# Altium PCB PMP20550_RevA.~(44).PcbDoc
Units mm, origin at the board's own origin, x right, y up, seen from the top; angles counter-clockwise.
Board outline 49.95 x 50.01 mm, 2 copper layers (Top Layer, Bottom Layer), stack 1.575 mm thick; 56 components, 23 nets, 129 pads, 17 vias.
Unrouted connection lines stored in the file: 113.
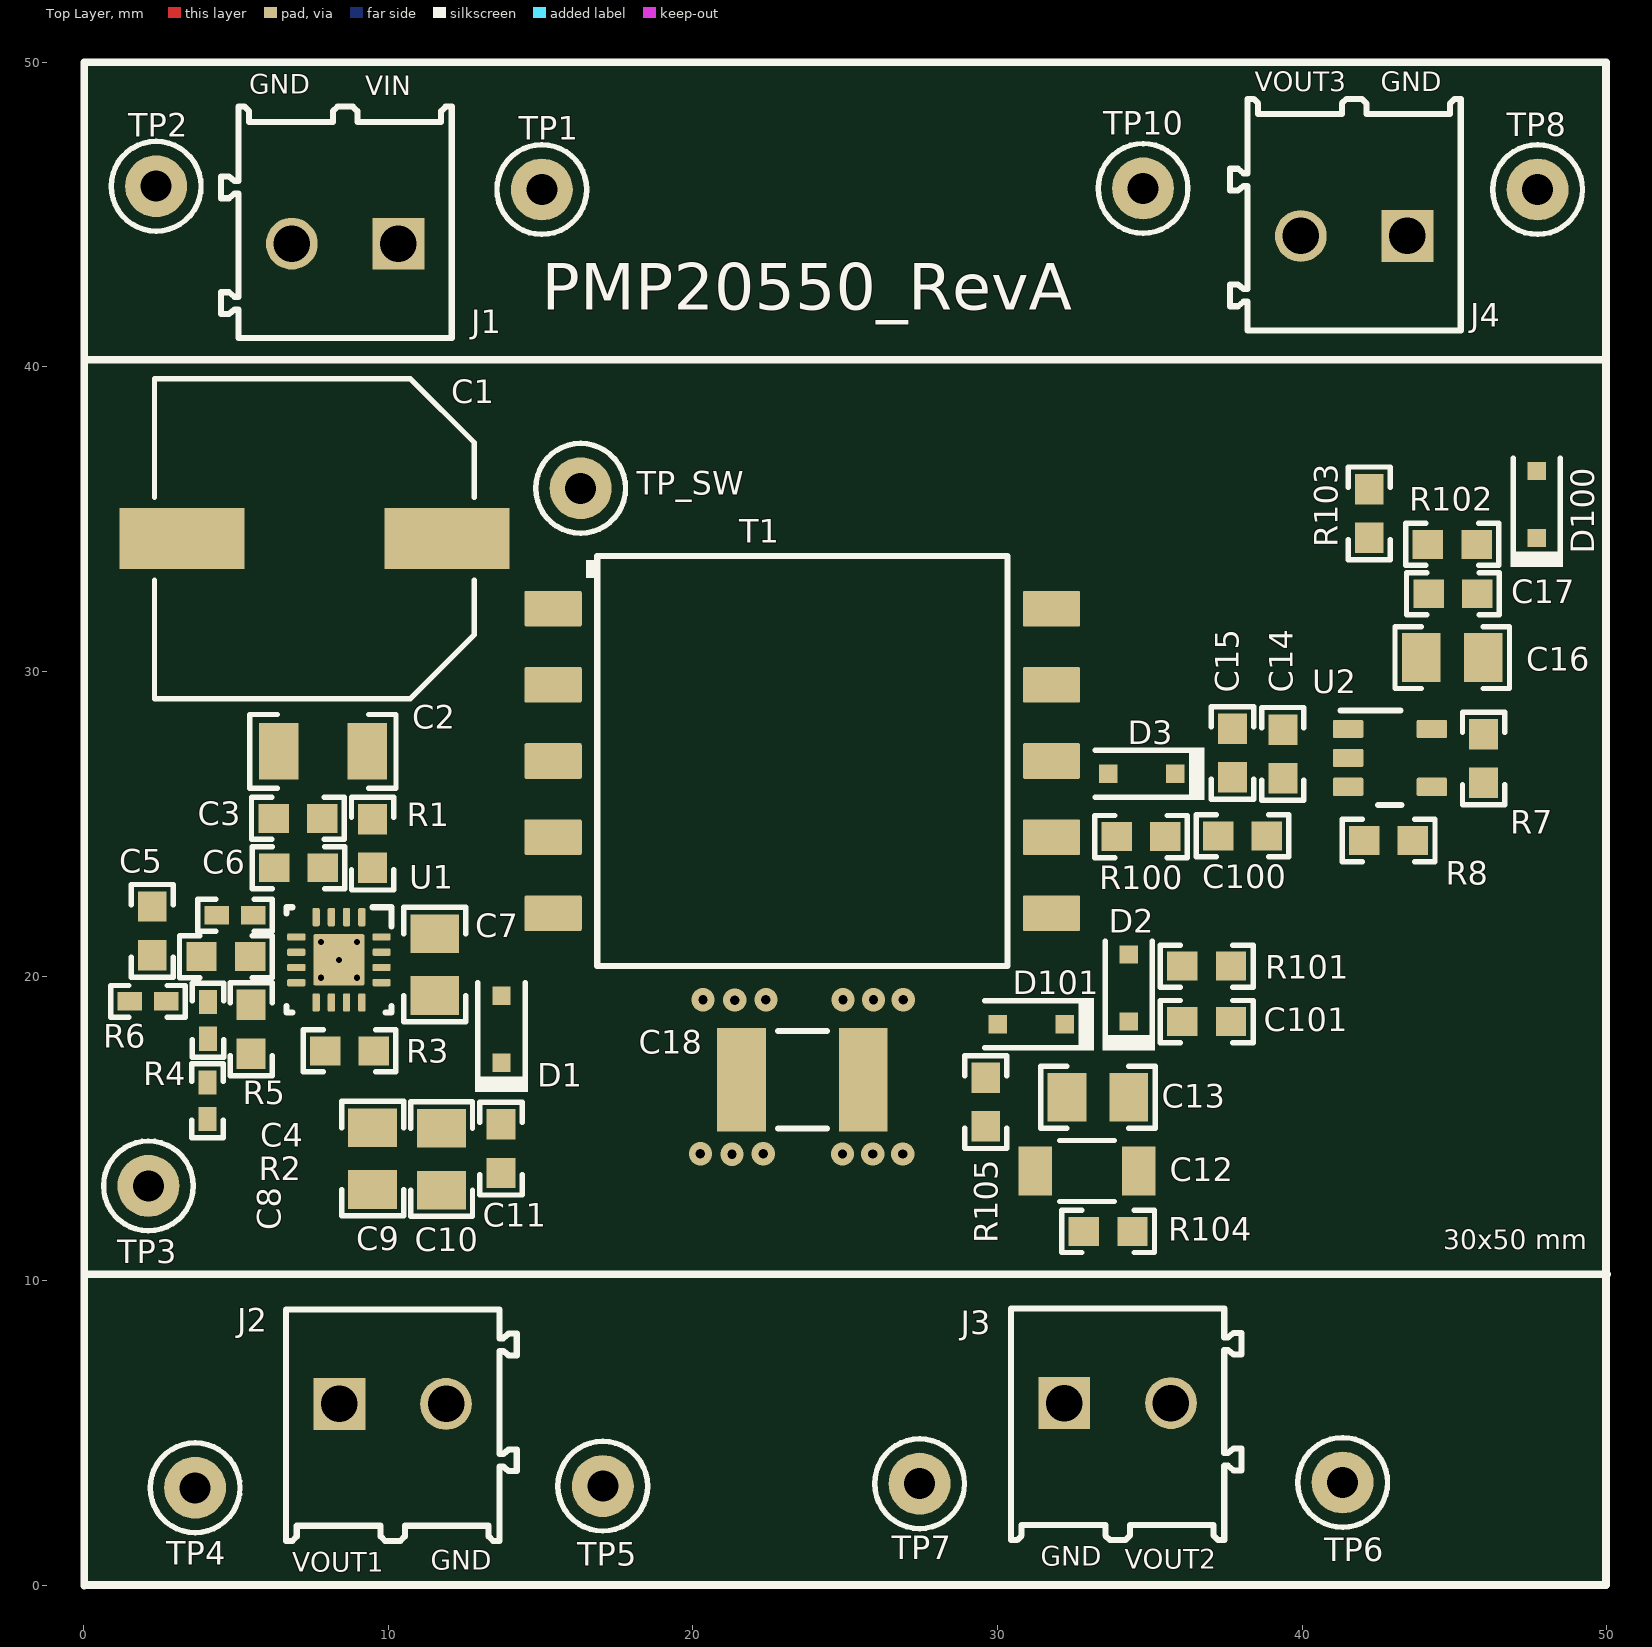
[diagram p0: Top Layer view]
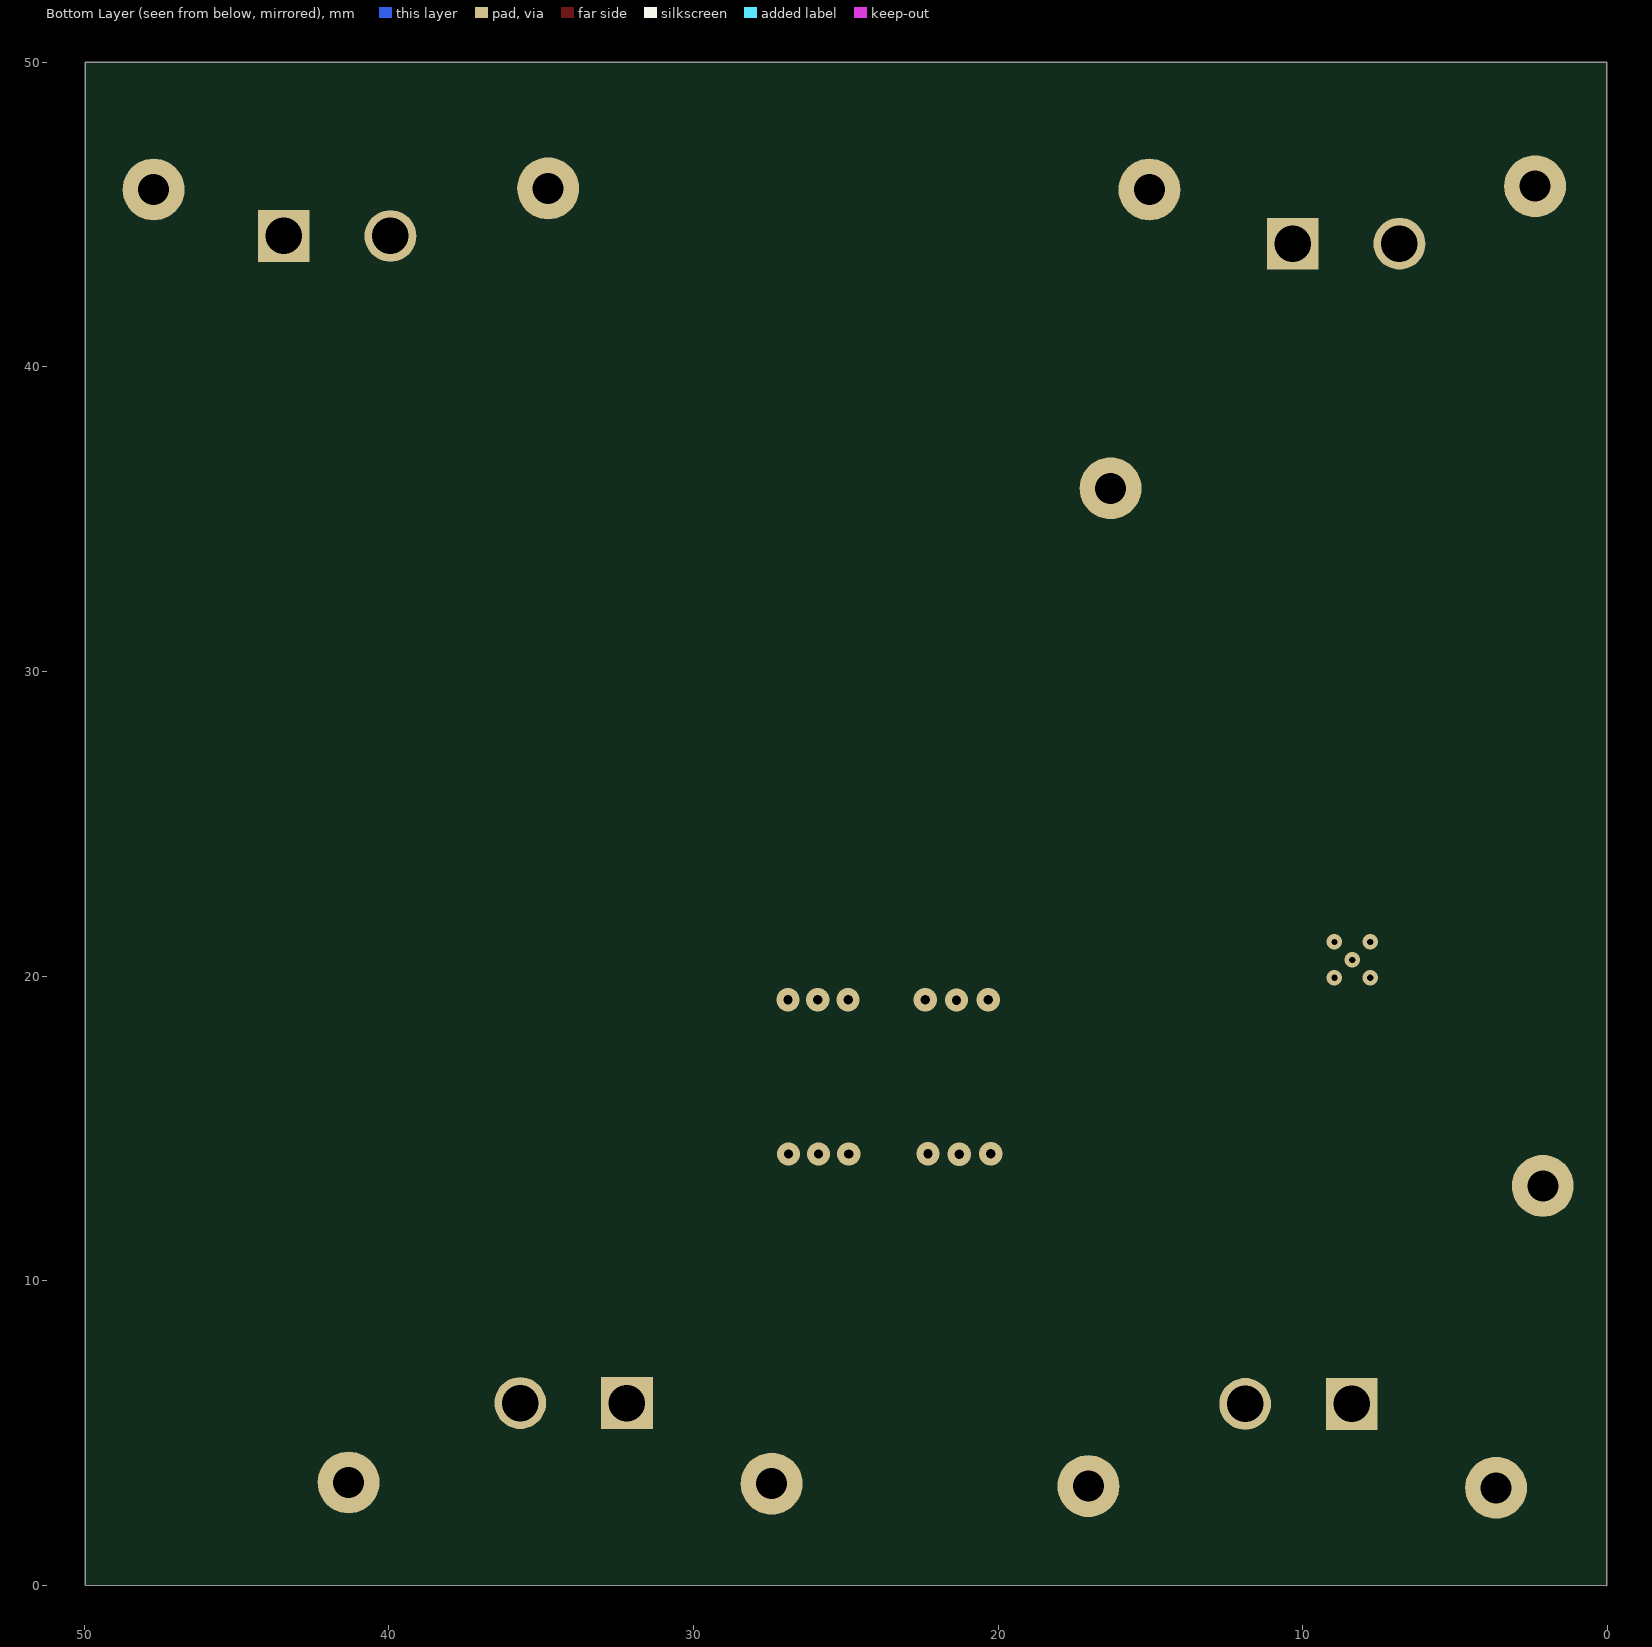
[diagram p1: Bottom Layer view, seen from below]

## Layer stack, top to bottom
Top Solder: solder mask 0.0102, Solder Resist, Dk 3.5
Top Layer: signal copper 0.0356
Dielectric1: core 1.5037, FR-4, Dk 4.8
Bottom Layer: signal copper 0.0356
Bottom Solder: solder mask 0.0102, Solder Resist, Dk 3.5

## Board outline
0.019,-0.011 0.019,49.996 0.021,49.994 49.97,49.994 49.972,49.992 49.972,0.008 49.971,0.01

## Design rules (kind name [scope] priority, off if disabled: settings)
AcuteAngle [All] p1: minimum=4.50000000000000E+0001 checktracksonly=FALSE
AssemblyTestPointUsage [All] p1: valid=2
BoardOutlineClearance BoardOutlineClearance_MountingHoles [OnCopper and InComponentClass('Mounting Holes')] p1: gap=1.016
BoardOutlineClearance BoardOutlineClearance_Poly [OnCopper and IsPoly] p2: gap=0.635
BoardOutlineClearance [OnCopper and Not InComponentClass('Logo') and not InComponentClass('FiducialMark') and not InRegion(1000,500,4000,800) and not InPoly] p3: gap=1.016
Clearance Clearance_Keepouts [((IsTrack Or IsArc) And Not InPoly) And IsFree and IsKeepOut vs ((IsTrack Or IsArc) And Not InPoly) And IsFree and IsKeepOut] p1: gap=0
Clearance Clearance_Poly [InPolygon] p2: gap=0.635
Clearance [All] p3: gap=0.2
ComponentClearance ComponentClearance_MountingHoles_FiducialMarks [InComponentClass('Mounting Holes') vs InComponentClass('FiducialMark')] p1: gap=1.27 collisioncheckmode=3 verticalgap=0.254 showdistances=FALSE
ComponentClearance ComponentClearance_Shunt [InComponentClass('Header') vs InComponentClass('Shunt')] p2: gap=0 collisioncheckmode=3 verticalgap=0 showdistances=FALSE
ComponentClearance ComponentClearance_Logo [InComponentClass('Logo')] p3: gap=1.27 collisioncheckmode=3 verticalgap=0.254 showdistances=FALSE
ComponentClearance ComponentClearance_ScrewToNut [(HasFootprint('NY PMS 440 0025 PH')) vs (HasFootprint('Keystone_1902C'))] p4: gap=0.127 collisioncheckmode=3 verticalgap=0.254 showdistances=FALSE
ComponentClearance ComponentClearance_MountingHoles [InComponentClass('Mounting Holes')] p5: gap=6.35 collisioncheckmode=3 verticalgap=2540 showdistances=FALSE
ComponentClearance ComponentClearance_SmallPassives [HasFootprint('0201*') or HasFootprint('0402*') or HasFootprint('0508') or HasFootprint('0603*') or HasFootprint('0612') or HasFootprint('0805*') or HasFootprint('0815*') or HasFootprint('0830*') or HasFootprint('1206*') or HasFootprint('1210*') or HasFootprint('1808*') or HasFootprint('1812*') or HasFootprint('1825*') or HasFootprint('2010*') or HasFootprint('2220*') or HasFootprint('2225*') or HasFootprint('2512*') or HasFootprint('2728*') or HasFootprint('3518*') vs HasFootprint('0201*') or HasFootprint('0402*') or HasFootprint('0508') or HasFootprint('0603*') or HasFootprint('0612') or HasFootprint('0805*') or HasFootprint('0815*') or HasFootprint('0830*') or HasFootprint('1206*') or HasFootprint('1210*') or HasFootprint('1808*') or HasFootprint('1812*') or HasFootprint('1825*') or HasFootprint('2010*') or HasFootprint('2220*') or HasFootprint('2225*') or HasFootprint('2512*') or HasFootprint('2728*') or HasFootprint('3518*')] p6: gap=0.38 collisioncheckmode=3 verticalgap=0.254 showdistances=FALSE
ComponentClearance ComponentClearance_THtoSMT [IsThruComponent vs IsSMTComponent] p7: gap=1.016 collisioncheckmode=3 verticalgap=0.762 showdistances=FALSE
ComponentClearance ComponentClearance_THtoTH [IsThruComponent vs IsThruComponent] p8: gap=0.762 collisioncheckmode=3 verticalgap=0.762 showdistances=FALSE
ComponentClearance [All] p9: gap=0.762 collisioncheckmode=3 verticalgap=0.254 showdistances=FALSE
DiffPairsRouting [All] p1: maxlimit=2.54 minlimit=0.254 mostfreqgap=0.254 toplayer_minwidth=0.381 toplayer_maxwidth=0.381 toplayer_prefwidth=0.381 bottomlayer_minwidth=0.381 bottomlayer_maxwidth=0.381 bottomlayer_prefwidth=0.381 maxuncoupledlength=25.4
FabricationTestPointUsage TestPointUsage [All] p1: valid=2 allowmultiple=FALSE
FabricationTestpoint Testpoint [All] p1: side=3 testpointundercomponent=TRUE minsize=1.016 maxsize=2.54 preferedsize=1.524 minholesize=0 maxholesize=1.016 preferedholesize=0.813 testpointgrid=0.025 allowsidetop=TRUE allowsidebottom=TRUE usegrid=TRUE gridtolerance=0
FanoutControl Fanout_LCC [IsLCC] p1: bgadir=Out bgaviamode=Centered fanoutstyle=Auto fanoutdirection=Alternating viagrid=0.025 // Fanout_LCC (Default Rule)
FanoutControl Fanout_BGA [IsBGA] p2: bgadir=Out bgaviamode=Centered fanoutstyle=Auto fanoutdirection=Alternating viagrid=0.025 // Fanout_BGA (Default Rule)
FanoutControl Fanout_Default [All] p4: bgadir=Out bgaviamode=Centered fanoutstyle=Auto fanoutdirection=Alternating viagrid=0.025 // Fanout_Default (Default Rule)
FanoutControl Fanout_Small [(CompPinCount < 5)] p5: bgadir=Out bgaviamode=Centered fanoutstyle=Auto fanoutdirection=OutThenIn viagrid=0.025 // Fanout_Small (Default Rule)
HoleSize [All] p1: absolutevalues=TRUE maxlimit=6.375 minlimit=0.2 maxpercent=80.000 minpercent=20.000
MinimumAnnularRing MinimumAnnularRing_ThermalPadVias [IsVia and InAnyComponent] p1: minimumring=0.15
MinimumAnnularRing [All] p2: minimumring=0.203
MinimumSolderMaskSliver MinimumSolderMaskSliver_Logo [InComponentClass('Logo') vs InComponentClass('Logo')] p1: minsoldermaskwidth=0.018
MinimumSolderMaskSliver [All] p2: minsoldermaskwidth=0.1
PlaneConnect [All] p1: planeconnectstyle=Direct reliefexpansion=0.254 reliefentries=4 reliefconductorwidth=0.254 reliefairgap=0.254
PolygonConnect [All] p1: connectstyle=Direct reliefconductorwidth=0.254 reliefentries=4 polygonreliefangle="90 Angle" airgapwidth=0.254
RoutingVias ThermalPadVias [IsVia and InAnyComponent] p1: holewidth=0.2 width=0.5 viastyle="Through Hole" minholewidth=0.2 minwidth=0.5 maxholewidth=0.33 maxwidth=0.6
RoutingVias [All] p2: holewidth=0.406 width=0.864 viastyle="Through Hole" minholewidth=0.2 minwidth=0.66 maxholewidth=1.016 maxwidth=1.651
SilkToBoardRegionClearance [Not ((IsComment or IsDesignator) And (Hide <> 'False')) and not InRegion(1000,500,4000,800)] p1:
SilkToSilkClearance SilkToSilkClearance_Pb-FreeLogo [(HasFootprint('Pb-Free_Overlay_Medium') OR HasFootprint('Pb-Free_Overlay_Small')) vs (HasFootprint('Pb-Free_Overlay_Medium') OR HasFootprint('Pb-Free_Overlay_Small'))] p1: silktosilkclearance=0
SilkToSilkClearance [All] p2: silktosilkclearance=0.102
SilkToSolderMaskClearance SilkToComponentPadClearance [IsPad and InAnycomponent] p1: minsilkscreentomaskgap=0.127 clearancetoexposedcopper=TRUE
SilkToSolderMaskClearance "Silk to Solder Mask Opening" [All] p2: minsilkscreentomaskgap=0.102 clearancetoexposedcopper=FALSE
SolderMaskExpansion [All] p1: expansion=0.05
Width [All] p1: maxlimit=2.54 minlimit=0.152 preferedwidth=0.254 checkconnectedcopper=TRUE
15 further rules are at their usual default settings.

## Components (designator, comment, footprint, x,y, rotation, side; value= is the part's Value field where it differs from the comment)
C1 "EEE-FC1V221P" SM_RADIAL_G 7.574,34.358 r180 top
C2 "GMK316AB7106KL" 1206 7.85,27.378 r180 top
C3 "C1608X7R1E104K080AA" 0603 7.031,25.179 r180 top
C4 "GRM155R71E333KA88D" 0402 4.962,21.998 r180 top
C5 "C1608X7R1E104K080AA" 0603 2.249,21.484 r90 top
C6 "C1608X7R1E104K080AA" 0603 7.048,23.556 r180 top
C7 "LMK212B7105KG-T" 0805_HV 11.52,20.379 r90 top
C8 "GRM1555C1H201JA01D" 0402 4.079,18.549 r90 top
C9 "GRM21BZ71A226ME15L" 0805_HV 9.483,14.008 r270 top
C10 "GRM21BZ71A226ME15L" 0805_HV 11.745,13.991 r270 top
C11 "C0603X104K8RACTU" 0603 13.696,14.336 r270 top
C12 "C3216X5R1E336M160AC" 1206_180 32.928,13.604 r180 top
C13 "08053C104KAT2A" 0805_HV 33.291,16.024 r180 top
C14 "GRM188Z71A106MA73D" 0603 39.362,27.294 r90 top
C15 "C1608X7R1E104K080AA" 0603 37.711,27.322 r90 top
C16 "C2012X7R1E474K125AA" 0805_HV 44.924,30.457 r180 top
C17 "C0603X104K8RACTU" 0603 44.947,32.552 r180 top
C18 "GR443QR73D102KW01L" 1812 23.59,16.598 r180 top
C100 "GRM1885C1H111JA01D" 0603 38.039,24.604 r180 top
C101 "GRM1885C1H111JA01D" 0603 36.861,18.506 r0 top
D1 "PMEG2020EJ,115" SOD-323F 13.713,18.255 r90 top
D2 "PMEG2020EJ,115" SOD-323F 34.302,19.612 r90 top
D3 "PMEG2020EJ,115" SOD-323F 34.728,26.641 r180 top
D100 "MMSZ5235BS-7-F" SOD-323 47.695,35.48 r90 top
D101 "MMSZ5235BS-7-F" SOD-323 31.101,18.418 r180 top
J1 "1984617" Phoenix_1984617 8.58,44.042 r180 top
J2 "1984617" Phoenix_1984617 10.143,5.956 r0 top
J3 "1984617" Phoenix_1984617 33.94,5.983 r0 top
J4 "1984617" Phoenix_1984617 41.703,44.297 r180 top
R1 "ERJ-3GEY0R00V" 0603 9.483,24.35 r90 top
R2 "RC0603FR-073K01L" 0603 4.666,20.638 r0 top
R3 "CRCW0603162KFKEA" 0603 8.723,17.547 r180 top
R4 "ERJ-2RKF49R9X" 0402 4.062,15.907 r270 top
R5 "CRCW060330K9FKEA" 0603 5.495,18.255 r270 top
R6 "ERJ-2RKF1002X" 0402 2.111,19.17 r0 top
R7 "RC0603FR-0778K7L" 0603 45.953,27.143 r90 top
R8 "CRCW060324K9FKEA" 0603 42.833,24.45 r0 top
R100 "CPF0603B1K62E" 0603 34.705,24.581 r180 top
R101 "CPF0603B1K62E" 0603 36.861,20.324 r180 top
R102 "CPF0603B1K62E" 0603 44.924,34.173 r180 top
R103 "CPF0603B1K62E" 0603 42.198,35.187 r270 top
R104 "CPF0603B1K62E" 0603 33.627,11.618 r180 top
R105 "CPF0603B1K62E" 0603 29.609,15.864 r270 top
T1 "750316553" Wurth_750316553 23.588,27.06 r0 top
TP1 "5000" Keystone5000 15.038,45.82 r90 top
TP2 "5001" Keystone5001 2.377,45.929 r90 top
TP3 "5003" Keystone5003 2.124,13.113 r0 top
TP4 "VBUS" Keystone5000 3.656,3.203 r90 top
TP5 "5001" Keystone5001 17.039,3.257 r90 top
TP6 "5000" Keystone5000 41.326,3.378 r0 top
TP7 "5001" Keystone5001 27.438,3.338 r0 top
TP8 "5000" Keystone5000 47.725,45.82 r0 top
TP10 "5001" Keystone5001 34.774,45.857 r90 top
TP_SW "5001" Keystone5001 16.312,36.013 r90 top
U1 "TPS55340QRTERQ1" RTE0016C 8.378,20.534 r270 top
U2 "TPS73201QDBVRQ1" DBV0005A_N 42.88,27.162 r0 top

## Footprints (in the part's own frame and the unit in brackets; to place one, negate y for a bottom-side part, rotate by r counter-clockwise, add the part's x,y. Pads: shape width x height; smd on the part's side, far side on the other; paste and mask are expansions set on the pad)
0402 [mm] "0402 from SM-752 data"
  rect 0.8x0.6 smd: 1(-0.6,0) 2(0.6,0)
  silkscreen extent -1.22,-0.52 1.22,0.52, body extent -0.55,-0.3 0.55,0.3, height 0.6
0603 [mm] "0603 from SM-752 data"
  rect 1x0.95 smd: 1(-0.8,0) 2(0.8,0)
  silkscreen extent -1.52,-0.69 1.52,0.69, body extent -0.87,-0.47 0.87,0.47, height 1
0805_HV [mil] "0805 with 30mil clearance between pads"
  rect 50x63 smd: 1(-40,0) 2(40,0)
  silkscreen extent -74,-40 74,40, body extent -43,-29 43,29, height 57
1206 [mm] "1206 from SM-752 data"
  rect 1.3x1.85 smd: 1(-1.45,0) 2(1.45,0)
  silkscreen extent -2.4,-1.21 2.4,1.21, body extent -1.7,-0.9 1.7,0.9, height 1.35
1206_180 [mm] "1206_180"
  rect 1.1x1.6 smd: 1(-1.7,0) 2(1.7,0)
  silkscreen extent -0.9,-1 0.9,1, body extent -1.75,-0.95 1.75,0.95, height 1.8
1812 [mm]
  rect 1.6x3.4 smd: 1(-2,0) 2(2,0)
  silkscreen extent -0.8,-1.6 0.8,1.6, body extent -2.4,-1.7 2.4,1.7, height 1.35
DBV0005A_N [mm] "SOT23, 5-Leads, Body 2.9x1.6mm, Pitch 0.95mm, Lead Span 2.8mm, IPC Medium Density"
  rrect17% 1x0.6 smd: 1(-1.375,0.95) 2(-1.375,0) 3(-1.375,-0.95) 4(1.375,-0.95) 5(1.375,0.95)
  silkscreen extent -1.63,-1.55 0.38,1.55, body extent -1.42,-1.46 1.42,1.46, height 1.09
Keystone5000 [mil] "For Keystone 500x miniature loop terminals"
  round 80 hole 40: 1(0,0)
  silkscreen extent -58,-58 58,58, body extent -49,-49 49,49, height 182
Keystone5001 [mil] "For Keystone 500x miniature loop terminals"
  round 80 hole 40: 1(0,0)
  silkscreen extent -58,-58 58,58, body extent -49,-49 49,49, height 182
Keystone5003 [mil] "For Keystone 500x miniature loop terminals"
  round 80 hole 40: 1(0,0)
  silkscreen extent -58,-58 58,58, body extent -49,-49 49,49, height 182
Phoenix_1984617 [mm] "Terminal Block, 3.5mm, 2x1, TH"
  rect 1.7x1.7 hole 1.2: 1(-1.75,0)
  round 1.7 hole 1.2: 2(1.75,0)
  silkscreen extent -3.5,-4.5 4.07,3.1, body extent -3.5,-4.5 4.07,3.1, height 9
RTE0016C [mm] "Texas Insturments"
  rrect42% 0.6x0.24 smd: 1(-1.4,0.75) 2(-1.4,0.25) 3(-1.4,-0.25) 4(-1.4,-0.75) 9(1.4,-0.75) 10(1.4,-0.25) 11(1.4,0.25) 12(1.4,0.75)
  rrect42% 0.24x0.6 smd: 5(-0.75,-1.4) 6(-0.25,-1.4) 7(0.25,-1.4) 8(0.75,-1.4) 13(0.75,1.4) 14(0.25,1.4) 15(-0.25,1.4) 16(-0.75,1.4)
  rrect6% 1.55x1.55 on Top Paste: 17(0,0)
  rrect6% 1.68x1.68 smd paste-0.85: 17(0,0)
  silkscreen extent -1.72,-1.73 1.72,1.73, body extent -1.57,-1.57 1.58,1.58, height 0.81
SM_RADIAL_G [mm] "10 x 10.2mm:  Panasonic G"
  rect 4.1x2 smd: 1(-4.35,0) 2(4.35,0)
  silkscreen extent -5.25,-5.25 5.25,5.25, body extent -5.25,-5.25 5.25,5.25, height 10.5
SOD-323 [mm] "NXP recommended land pattern"
  rect 0.6x0.6 smd paste-0.05: 1(-1.1,0) 2(1.1,0)
  silkscreen extent -2.06,-0.86 1.53,0.86, body extent -1.3,-0.67 1.3,0.68, height 1.1
SOD-323F [mm] "NXP recommended land pattern"
  rect 0.6x0.6 smd paste-0.05: 1(-1.1,0) 2(1.1,0)
  silkscreen extent -2.06,-0.86 1.53,0.86, body extent -1.35,-0.67 1.35,0.68, height 0.79
Wurth_750316553 [mm] "SMD, 10-Leads, Body 17.75x13.46mm, Pitch 2.5mm"
  rrect9% 1.88x1.17 smd: 1(-8.18,5) 2(-8.18,2.5) 3(-8.18,0) 4(-8.18,-2.5) 5(-8.18,-5) 6(8.18,-5) 7(8.18,-2.5) 8(8.18,0) 9(8.18,2.5) 10(8.18,5)
  silkscreen extent -7.1,-6.73 6.73,6.73, body extent -8.87,-6.73 8.88,6.73, height 12.7

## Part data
C1: "CAP, AL, 220 µF, 35 V, +/- 20%, 0.15 ohm, SMD"
C2: "CAP, CERM, 10 µF, 35 V, +/- 10%, X7R, 1206"
C3 C5 C6 C15: "CAP, CERM, 0.1 µF, 25 V, +/- 10%, X7R, 0603"
C4: "OPEN, 0402"
C7: "CAP, CERM, 1 µF, 10 V, +/- 10%, X7R, 0805"
C8: "CAP, CERM, 200 pF, 50 V, +/- 5%, C0G/NP0, 0402"
C9 C10: "CAP, CERM, 22 µF, 10 V, +/- 20%, X7R, 0805"
C11 C17: "CAP, CERM, 0.1 µF, 10 V, +/- 10%, X7R, 0603"
C12: "CAP, CERM, 33 µF, 25 V, +/- 20%, X5R, 1206"
C13: "CAP, CERM, 0.1 µF, 25 V, +/- 10%, X7R, 0805"
C14: "CAP, CERM, 10 µF, 10 V, +/- 20%, X7R, 0603"
C16: "CAP, CERM, 4.7 µF, 25 V, +/- 10%, X7R, 0805"
C18: "CAP, CERM, 1000 pF, 2000 V, +/- 10%, X7R, 1812"
C100 C101: "CAP, CERM, 110 pF, 50 V, +/- 5%, C0G/NP0, 0603"
D1 D2 D3: "Diode, Schottky, 20 V, 2 A, SOD-323F"
D100 D101: "Diode, Zener, 6.8 V, 200 mW, SOD-323"
J1 J2 J3 J4: "Terminal Block, 3.5mm, 2x1, TH"
R1: "RES, 0, 5%, 0.1 W, 0603"
R2: "RES, 3.01 k, 1%, 0.1 W, 0603"
R3: "RES, 162 k, 1%, 0.1 W, 0603"
R4: "RES, 49.9, 1%, 0.1 W, AEC-Q200 Grade 0, 0402"
R5: "RES, 30.9 k, 1%, 0.1 W, 0603"
R6: "RES, 10.0 k, 1%, 0.1 W, 0402"
R7: "RES, 78.7 k, 1%, 0.1 W, 0603"
R8: "RES, 24.9 k, 1%, 0.1 W, 0603"
R100 R101 R102 R103 R104 R105: "RES, 1.62 k, 0.1%, 0.063 W, 0603"
T1: "Transformer, 52 uH, SMT"
TP1 TP6 TP8: "Test Point, Miniature, Red, TH"
TP2 TP5 TP7 TP10 TP_SW: "Test Point, Miniature, Black, TH"
TP3: "Test Point, Miniature, Orange, TH"
TP4: library part 5000, "Test Point, TH, Miniature, Red"
U1: "Integrated 5-A 40-V Wide Input Range Boost/SEPIC/Flyback DC-DC Regulator, RTE0016C"
U2: "Single Output Fast Transient Response LDO, 250 mA, Adjustable 1.2 to 5.5 V Output, 1.7 to 5.5 V Input, 5-pin SOT-23 (DBV), -40 to 125 degC, Green (RoHS & no Sb/Br)"

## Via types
v1: diameter 0.762, hole 0.305, Top Layer to Bottom Layer, 12 vias
v2: diameter 0.5, hole 0.2, Top Layer to Bottom Layer, tented top, 5 vias

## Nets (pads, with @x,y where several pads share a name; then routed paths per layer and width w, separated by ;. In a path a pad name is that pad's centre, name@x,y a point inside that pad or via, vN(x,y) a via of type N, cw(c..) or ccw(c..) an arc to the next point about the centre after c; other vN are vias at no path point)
GND: C1.2 C2.2 C3.2 C4.2 C5.2 C6.2 C9.2 C10.2 C11.2 C18.2 J1.2 J2.2 R3.1 R6.1 T1.4 TP2.1 TP5.1 U1.5 U1.6 U1.11 U1.12 U1.13 U1.17@8.378,20.534
  other v1: 21.281,14.151 20.242,14.166 22.306,14.166 21.369,19.211 20.33,19.225 22.393,19.225
  other v2: 7.788,19.944 8.968,19.944 8.378,20.534 7.788,21.124 8.968,21.124
GND2: C12.2 C13.2 C14.2 C15.2 C16.2 C17.2 C18.1 J3.1 J4.2 R8.1 R102.2 R103.2 R104.2 R105.2 T1.10 TP7.1 TP10.1 U2.2
  other v1: 24.907,14.157 25.902,14.157 26.883,14.157 24.927,19.225 25.922,19.225 26.903,19.225
NetC1_1: C1.1 C2.1 J1.1 R1.2 T1.3 TP1.1
NetC3_1: C3.1 R1.1 U1.2 U1.3
NetC4_1: C4.1 R2.2 U1.7
NetC5_1: C5.1 R2.1
NetC6_1: C6.1 U1.4
NetC7_1: C7.1 D1.2 T1.5
NetC7_2: C7.2 T1.1 TP_SW.1 U1.1 U1.15 U1.16
NetC8_1: C8.1 R4.1 R5.2 TP3.1
NetC8_2: C8.2 R5.1 R6.2 U1.8
NetC9_1: C9.1 C10.1 C11.1 D1.1 J2.1 R4.2 TP4.1
NetC12_1: C12.1 C13.1 C101.1 D2.1 D101.1 J3.2 R104.1 TP6.1
NetC14_1: C14.1 C15.1 C100.1 D3.1 U2.1 U2.3
NetC16_1: C16.1 C17.1 D100.1 J4.1 R7.2 R102.1 TP8.1 U2.5
NetC100_2: C100.2 R100.1
NetC101_2: C101.2 R101.1
NetD2_2: D2.2 R101.2 T1.6
NetD3_2: D3.2 R100.2 T1.7 T1.8
NetD100_2: D100.2 R103.1
NetD101_2: D101.2 R105.1
NetR3_2: R3.2 U1.9
NetR7_1: R7.1 R8.2 U2.4
pads on no net: T1.2 T1.9 U1.10 U1.14 U1.17@8.378,20.534

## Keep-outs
Keep-Out Layer:
  text ".Layer_Name" at 14.656,-21.806 h1.52

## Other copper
Top Layer:
  text ".Layer_Name" at 14.656,-21.806 h1.52
Bottom Layer:
  text ".Layer_Name" at 14.656,-21.806 h1.52

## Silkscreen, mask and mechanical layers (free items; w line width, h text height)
Top Overlay:
  lines w0.254: 0.019,-0.011 0.019,49.996 0.021,49.994 49.97,49.994 49.972,49.992 49.972,0.008 49.971,0.01 0.04,0.01 ; 0.035,10.211 50.001,10.211 ; 0.055,40.233 49.927,40.233
  text "VOUT3" at 38.438,49.049 h0.64
  text "GND" at 42.574,49.049 h0.64
  text "GND" at 5.426,48.964 h0.64
  text "VIN" at 9.245,48.921 h0.64
  text "PMP20550_RevA" at 15.028,41.876 h1.52
  text "30x50 mm" at 44.623,11.025 h0.64
  text "GND" at 31.416,0.649 h0.64
  text "VOUT2" at 34.168,0.553 h0.64
  text "GND" at 11.397,0.504 h0.64
  text "VOUT1" at 6.845,0.45 h0.64
  text ".Layer_Name" at 14.656,-21.806 h1.52
Bottom Overlay:
  text ".Layer_Name" at 14.656,-21.806 h1.52
Top Paste:
  text ".Layer_Name" at 14.656,-21.806 h1.52
Bottom Paste:
  text ".Layer_Name" at 14.656,-21.806 h1.52
Top Solder:
  text ".Layer_Name" at 14.656,-21.806 h1.52
  text ".Layer_Name" at 14.656,-21.806 h1.52
Bottom Solder:
  text ".Layer_Name" at 14.656,-21.806 h1.52
Drill Guide:
  text ".Layer_Name" at 14.656,-21.806 h1.52
M1 Board Outline:
  text ".Layer_Name" at 14.656,-21.806 h1.52
M2 Board Dimensions:
  rectangle: 0,-6.985 3.175,-3.81
  rectangle: 3.175,-10.16 12.7,-6.985
  lines w0.178: 0,-6.985 25.4,-6.985 ; 3.175,-10.16 3.175,-3.81 ; 6.35,-10.16 6.35,-3.81 ; 12.7,-10.16 12.7,-3.81 ; 19.05,-10.16 19.05,-3.81 ; 0,-10.16 25.4,-10.16 25.4,-3.81 0,-3.81 0,-10.16
  text ".Layer_Name" at 14.656,-21.806 h1.52
M3 3D STEP Top:
  text ".Layer_Name" at 14.656,-21.806 h1.52
M4 3D STEP Bottom:
  text ".Layer_Name" at 14.656,-21.806 h1.52
M5 Assembly Top:
  lines w0.254: -7.417,-23.626 160.223,-23.626 ; -7.417,-18.462 160.274,-18.462 ; -7.417,-13.297 -7.417,-28.791 94.31,-28.791 160.274,-28.791 160.274,-13.297 -7.404,-13.297 -7.404,-28.791 32.614,-28.791 ; 55.194,-28.791 55.194,-13.297 ; 87.376,-18.462 87.376,-13.297 ; 108.712,-18.462 108.712,-13.297 ; 124.511,-28.956 124.511,-23.804
  text "COMPONENTS MARKED 'DNP' SHOULD NOT BE POPULATED." at 29.299,-8.09 h1.52
  text "ASSEMBLY VARIANT:" at 29.286,-11.024 h1.52
  text ".VariantName" at 55.601,-11.024 h1.52
  text "PCB VIEWED FROM TOP SIDE" at -5.804,-16.654 h1.52
  text "BOARD #:" at 57.099,-16.654 h1.52
  text ".PRJ_Number" at 70.955,-16.654 h1.52
  text "REV:" at 92.405,-16.654 h1.52
  text ".PCB_Rev" at 99.809,-16.654 h1.52
  text "SVN REV:" at 113.69,-16.654 h1.52
  text ".VersionControl_RevNumber" at 126.543,-16.654 h1.52
  text "TID #:" at 57.099,-21.819 h1.52
  text ".TID" at 70.955,-21.819 h1.52
  text "PLOT NAME =" at -5.804,-27.034 h1.52
  text ".plot_File_Name" at 14.656,-27.034 h1.52
  text "GENERATED    :" at 57.15,-27.034 h1.52
  text ".Print_Date" at 79.235,-27.034 h1.52
  text ".Print_Time" at 97.752,-27.034 h1.52
  text "TEXAS INSTRUMENTS" at 129.87,-27.034 h1.52
M6 Assembly Bottom:
  lines w0.254: -7.429,-18.474 160.261,-18.474 ; -7.379,-23.639 160.261,-23.639 ; 28.334,-28.969 28.334,-23.817 ; 44.133,-18.474 44.133,-13.31 ; 65.468,-18.474 65.468,-13.31 ; 97.65,-28.804 97.65,-13.31 ; 120.231,-28.804 160.249,-28.804 160.249,-13.31 -7.429,-13.31 -7.429,-28.804 58.534,-28.804 160.261,-28.804 160.261,-13.31
  text "COMPONENTS MARKED 'DNP' SHOULD NOT BE POPULATED." at 154.991,-8.077 h1.52
  text ".VariantName" at 128.473,-11.024 h1.52
  text "ASSEMBLY VARIANT:" at 154.864,-11.024 h1.52
  text ".VersionControl_RevNumber" at 26.302,-16.667 h1.52
  text "SVN REV:" at 39.154,-16.667 h1.52
  text ".PCB_Rev" at 53.035,-16.667 h1.52
  text "REV:" at 60.439,-16.667 h1.52
  text ".PRJ_Number" at 81.89,-16.667 h1.52
  text "BOARD #:" at 95.745,-16.667 h1.52
  text "PCB VIEWED FROM BOTTOM SIDE" at 158.648,-16.667 h1.52
  text ".TID" at 81.89,-21.831 h1.52
  text "TID #:" at 95.745,-21.831 h1.52
  text "TEXAS INSTRUMENTS" at 22.974,-27.047 h1.52
  text ".Print_Time" at 55.093,-27.047 h1.52
  text ".Print_Date" at 73.609,-27.047 h1.52
  text "GENERATED    :" at 95.694,-27.047 h1.52
  text ".plot_File_Name" at 138.189,-27.047 h1.52
  text "PLOT NAME =" at 158.648,-27.047 h1.52
M9 Title Sheet:
  drawing of 57 lines, arcs and shapes, not listed
  text "1" at 18.792,204.127 h1.78
  text "2" at 82.182,204.127 h1.78
  text "3" at 145.411,204.127 h1.78
  text "4" at 209.08,204.127 h1.78
  text "5" at 272.555,204.127 h1.78
  text "6" at 336.182,204.127 h1.78
  text "A" at -10.579,175.095 h1.78
  text "A" at 365.341,175.095 h1.78
  text "B" at -10.579,114.643 h1.78
  text "B" at 365.341,114.643 h1.78
  text "C" at -10.579,54.318 h1.78
  text "C" at 365.341,54.318 h1.78
  text "PROJECT TITLE:" at 288.125,7.048 h1.14
  text ".PRJ_Title" at 289.395,3.662 h1.78
  text "DESIGNED FOR:" at 288.125,-0.597 h1.14
  text ".PRJ_Customer" at 289.395,-4.153 h1.78
  text "D" at -10.579,-5.88 h1.78
  text "D" at 365.341,-5.88 h1.78
  text "FILE NAME:" at 288.125,-8.217 h1.14
  text ".PCB_File_Name_No_Path" at 289.395,-11.265 h1.78
  text "Texas Instruments (TI) and/or its licensors do not warrant the accuracy or completeness of this specification" at 161.9,-15.376 h1.14
  text "ENGINEER:" at 288.125,-15.583 h1.14
  text "LAYOUT BY:" at 326.352,-15.583 h1.14
  text "or any information contained therein. TI and/or its licensors do not warrant that this design will meet" at 160.757,-18.237 h1.14
  text ".PRJ_Engineer" at 289.395,-19.52 h1.78
  text ".PCB_Layout" at 327.635,-19.52 h1.78
  text "the specifications, will be suitable for your application or fit for any particular purpose, or will operate in" at 160.757,-21.099 h1.14
  text ".Layer_Name" at 14.656,-21.806 h1.52
  text "ALTIUM DESIGNER VERSION:" at 326.352,-23.457 h1.14
  text "an implementation. TI and/or its licensors do not warrant that the design is production worthy. You should" at 160.757,-23.961 h1.14
  text "completely validate and test your design implementation to confirm the system functionality for your application." at 161.9,-26.822 h1.14
  text ".print_Scale" at 289.395,-26.843 h1.78
  text ".Application_BuildNumber" at 327.635,-26.843 h1.78
  text "1" at 18.792,-32.093 h1.78
  text "2" at 82.182,-32.093 h1.78
  text "3" at 145.411,-32.093 h1.78
  text "4" at 209.08,-32.093 h1.78
  text "5" at 272.555,-32.093 h1.78
  text "6" at 336.182,-32.093 h1.78
M10 Fab Notes:
  drawing of 173 lines, arcs and shapes, not listed
  text "DESIGN INFORMATION" at 314.402,157.505 h1.52
  text "MIN. TRACK WIDTH:" at 298.03,152.933 h1.52
  text "8" at 325.874,152.933 h1.52
  text "MIL" at 329.805,152.933 h1.52
  text "MIN. CLEARANCE:" at 298.03,149.581 h1.52
  text "0.2" at 324.35,149.581 h1.52
  text "mm" at 329.805,149.581 h1.52
  text "MIN. VIA PAD SIZE:" at 298.03,146.228 h1.52
  text "24" at 325.113,146.228 h1.52
  text "MIL" at 329.805,146.228 h1.52
  text "0.05mm (2MIL)" at 315.683,142.628 h1.52
  text "MINIMUM ANNULAR RING" at 289.667,142.52 h1.52
  text "EXTERNAL" at 333.666,142.52 h1.52
  text "PER" at 294.747,139.522 h1.52
  text "IPC-D-275 CLASS 2 LEVEL C" at 300.335,139.522 h1.52
  text "MIL, HOLES" at 338.136,136.67 h1.52
  text "+/-" at 328.168,136.652 h1.52
  text "+/-" at 349.86,136.652 h1.52
  text "REGISTRATION TOLERANCES:" at 289.667,136.525 h1.52
  text "METAL" at 320.142,136.525 h1.52
  text "5" at 334.777,136.525 h1.52
  text "3" at 355.935,136.525 h1.52
  text "MIL" at 358.888,136.525 h1.52
  text "+/-" at 349.86,133.655 h1.52
  text "HOLE SIZE TOLERANCE (UNLESS OTHERWISE SPECIFIED):" at 289.667,133.528 h1.52
  text "3" at 355.935,133.528 h1.52
  text "MIL" at 358.888,133.528 h1.52
  text "MATERIAL:" at 287.768,128.208 h1.52
  text "FR-4 High Tg" at 312.824,124.643 h1.52
  text "FR-408" at 298.462,124.425 h1.52
  text "OTHER" at 336.257,124.425 h1.52
  text "X" at 308.889,124.333 h1.52
  text "62 MIL (1.6mm) +/-10%" at 306.592,120.292 h1.52
  text "THICKNESS:" at 289.667,120.184 h1.52
  text "X" at 303.337,120.184 h1.52
  text "OTHER" at 339.229,120.184 h1.52
  text "TOLERANCE:" at 289.667,116.17 h1.52
  text "X" at 310.986,116.17 h1.52
  text "ANSI IPC-6012 TYPE 3 CLASS 2" at 315.734,116.17 h1.52
  text "OTHER +/-" at 315.734,112.208 h1.52
  text "BOW & TWIST:" at 289.667,108.22 h1.52
  text "X" at 310.986,108.22 h1.52
  text "ANSI IPC-6012 TYPE 3 CLASS 2" at 315.734,108.22 h1.52
  text "OTHER +/-" at 315.734,104.194 h1.52
  text "DRILLING:" at 287.768,100.676 h1.52
  text "REFERENCE:" at 289.667,97.705 h1.52
  text "X" at 306.132,97.705 h1.52
  text "AS SHOWN" at 310.882,97.705 h1.52
  text "X" at 329.018,97.705 h1.52
  text "NC_DRILL FILES" at 332.498,97.705 h1.52
  text "PTH COPPER THICKNESS:" at 289.667,93.691 h1.52
  text "X" at 318.375,93.691 h1.52
  text "20-30 um" at 321.855,93.691 h1.52
  text "OTHER" at 340.067,93.691 h1.52
  text "BOARD FINISH:" at 287.768,89.653 h1.52
  text "SILKSCREEN:" at 291.711,86.656 h1.52
  text "X" at 315.81,86.656 h1.52
  text "TOP" at 319.01,86.656 h1.52
  text "X" at 328.764,86.656 h1.52
  text "BOTTOM" at 331.99,86.656 h1.52
  text "SILKSCREEN COLOR:" at 291.711,82.414 h1.52
  text "X" at 315.783,82.414 h1.52
  text "WHITE" at 319.01,82.414 h1.52
  text "OTHER" at 331.99,82.414 h1.52
  text "X" at 319.111,78.37 h1.52
  text "GREEN" at 322.338,78.37 h1.52
  text "OTHER" at 338.035,78.37 h1.52
  text "SOLDER RESIST COLOR:" at 291.711,78.096 h1.52
  text "X" at 319.111,74.052 h1.52
  text "MATTE" at 322.338,74.052 h1.52
  text "SEMI-GLOSS" at 338.023,74.036 h1.52
  text "IMMERSION GOLD (ENIG)" at 314.718,69.264 h1.52
  text "ENEPIG" at 348.691,69.18 h1.52
  text "SURFACE FINISH:" at 287.768,69.155 h1.52
  text "X" at 309.969,69.155 h1.52
  text "IMM. TIN/SILVER OR EQUIV" at 296.139,65.167 h1.52
  text "OTHER" at 332.498,65.167 h1.52
  text "ARRAY/PANEL:" at 287.768,60.621 h1.52
  text "CUT AND TRIM PER M1 BOARD OUTLINE" at 314.718,60.512 h1.52
  text "N.C. ROUTE" at 314.718,56.658 h1.52
  text "X" at 331.964,56.658 h1.52
  text "V. SCORE" at 336.714,56.658 h1.52
  text "CERTIFICATION:" at 287.768,53.178 h1.52
  text "MATERIALS AND WORKMANSHIP FOR ALL PCBS" at 306.183,53.178 h1.52
  text "TO MEET OR EXCEED THE REQUIREMENTS OF:" at 306.183,50.689 h1.52
  text "X" at 296.696,47.222 h1.52
  text "ANSI IPC-A-600F CLASS ->" at 300.227,47.222 h1.52
  text "X" at 341.859,47.222 h1.52
  text "2" at 344.88,47.222 h1.52
  text "1" at 336.879,47.184 h1.52
  text "3" at 353.872,47.184 h1.52
  text "X" at 317.373,43.171 h1.52
  text "RoHS" at 320.852,43.171 h1.52
  text "OTHER" at 337.22,43.171 h1.52
  text "PER ORDER" at 347.305,43.171 h1.52
  text "ALL BOARDS MUST MEET OR EXCEED UL94-V0 REQUIREMENTS." at 288.468,38.964 h1.52
  text "PCB MUST BEAR THE UL94V-0 UL REGISTERED MATERIAL ID NUMBER" at 288.468,35.916 h1.52
  text "ADDITIONAL REQUIREMENTS:" at 287.768,31.512 h1.52
  text "MICROSECTION:" at 289.667,28.591 h1.52
  text "YES" at 312.673,28.591 h1.52
  text "REQUIRED" at 334.555,24.625 h1.52
  text "BARE BOARD ELEC. TEST:" at 289.667,24.553 h1.52
  text "NONE" at 322.833,24.553 h1.52
  text "X" at 331.329,24.553 h1.52
  text "PER ORDER" at 349.592,24.553 h1.52
  text ".Layer_Name" at 14.656,-21.806 h1.52
M11 Gerber Information:
  lines w0.254: -7.417,-23.626 160.223,-23.626 ; -7.417,-18.462 160.274,-18.462 ; -7.417,-13.297 -7.417,-28.791 94.31,-28.791 160.274,-28.791 160.274,-13.297 -7.404,-13.297 -7.404,-28.791 32.614,-28.791 ; 55.194,-28.791 55.194,-13.297 ; 87.376,-18.462 87.376,-13.297 ; 108.712,-18.462 108.712,-13.297 ; 124.511,-28.956 124.511,-23.804
  text "ALL ARTWORK VIEWED FROM TOP SIDE" at -5.804,-16.654 h1.52
  text "BOARD #:" at 57.099,-16.654 h1.52
  text ".PRJ_Number" at 70.955,-16.654 h1.52
  text "REV:" at 92.405,-16.654 h1.52
  text ".PCB_Rev" at 99.809,-16.654 h1.52
  text "SVN REV:" at 113.69,-16.654 h1.52
  text ".VersionControl_RevNumber" at 126.543,-16.654 h1.52
  text "LAYER NAME =" at -5.804,-21.806 h1.52
  text "TID #:" at 57.099,-21.819 h1.52
  text ".TID" at 70.955,-21.819 h1.52
  text "PLOT NAME =" at -5.804,-27.034 h1.52
  text ".plot_File_Name" at 14.656,-27.034 h1.52
  text "GENERATED    :" at 57.15,-27.034 h1.52
  text ".Print_Date" at 79.235,-27.034 h1.52
  text ".Print_Time" at 97.752,-27.034 h1.52
  text "TEXAS INSTRUMENTS" at 129.87,-27.034 h1.52
M12 Stackup:
  text ".Layer_Name" at 14.656,-21.806 h1.52
M13 Component Bodies Top:
  text ".Layer_Name" at 14.656,-21.806 h1.52
M14 Component Bodies Bottom:
  text ".Layer_Name" at 14.656,-21.806 h1.52
M15 Courtyards Top:
  text ".Layer_Name" at 14.656,-21.806 h1.52
M16 Courtyards Bottom:
  text ".Layer_Name" at 14.656,-21.806 h1.52
Drill Drawing:
  text ".Layer_Name" at 14.656,-21.806 h1.52
M17 Embedded Cavity:
  text ".Layer_Name" at 14.656,-21.806 h1.52
M18 Embedded Assembly:
  text ".Layer_Name" at 14.656,-21.806 h1.52
M19 Embedded Keepout:
  text ".Layer_Name" at 14.656,-21.806 h1.52

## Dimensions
0,-10.16 to 25.4,-10.16 on M2 Board Dimensions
